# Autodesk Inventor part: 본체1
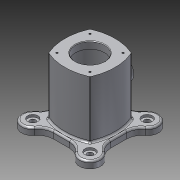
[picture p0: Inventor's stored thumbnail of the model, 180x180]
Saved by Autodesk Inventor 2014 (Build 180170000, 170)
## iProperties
Created: 2016-05
Part Number: 본체1
Material: 알루미늄 6061
Document SubType Name: Modeling
Designer: Administrator
Density: 2.71 g/cm^3
Appearance: 알루미늄 - 평지
Mass: 1111.1 g
Surface Area: 865.598 cm^2
Volume: 409.999 cm^3
Author: Administrator
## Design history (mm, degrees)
sketch "스케치1" dims "d1" = 70
  geometry: L1 (-49, 49)-(49, 49); L2 (49, 49)-(49, -49); L3 (49, -49)-(-49, -49); L4 (-49, -49)-(-49, 49); L5 (0, 0)-(-49.497, 49.497); L6 (0, 0)-(0, 49); C1 r 18 at (-49.497, 49.497); C2 r 18 at (-49.497, -49.497); C3 r 18 at (49.497, -49.497); C4 r 18 at (49.497, 49.497); 2 further points
  constraints: 12 end point, 4 centre point, 3 parallel, 2 midpoint, 1 coincident, 1 horizontal, 1 horizontal alignment, 1 perpendicular, 1 vertical alignment, 12 other
  dimensions: "d2" = 98 distance of L2.end L3.end; "d3" = 98 distance of L1.end L2.end; "d4" = 45 deg angle of L5 L6; "d6" = 18 radius of C1; "d9" = 360 deg dimension on point (0, 0) L5.end (derived)
extrude "돌출1" new body sketch "스케치1" distance "d11" = 12; taper "d12" = 0 deg
hole "구멍1" diameter "d15" = 10; stored, may be unused: countersink angle "d19" = 90 deg, drill point angle "d21" = 118 deg; dims "d13" = 10, "d14" = 10, "d16" = 6, "d17" = 18, "d18" = 4, "d20" = 8
fillet "모깎기1" dims "d28" = 25
sketch "스케치2"
  geometry: L1 (0, 0)-(-28.284, 28.284); L2 (0, 0)-(0, 40); A1 r 40 centre (0, 0) between (0, 40) and (-28.284, 28.284); 2 further points
  constraints: 4 end point, 2 coincident, 2 point on circle, 1 centre point
  dimensions: "d31" = 40 radius of A1; "d32" = 45 deg angle of L2 L1
hole "구멍2" sketch "스케치2" at (-28.284, 28.284) diameter "d33" = 3.242; stored, may be unused: countersink angle "d37" = 90 deg, drill point angle "d39" = 120 deg; dims "d34" = 7, "d35" = 18, "d36" = 4, "d38" = 10
sketch "스케치3"
  geometry: L1 (-43, 43)-(43, 43); L2 (43, 43)-(43, -43); L3 (43, -43)-(-43, -43); L4 (-43, -43)-(-43, 43); L5 (-35.355, 35.355)-(35.355, 35.355); L6 (35.355, 35.355)-(35.355, -35.355); L7 (35.355, -35.355)-(-35.355, -35.355); L8 (-35.355, -35.355)-(-35.355, 35.355); L9 (0, 0)-(-43, 43); L10 (0, 0)-(43, 43); A1 r 85.963 centre (43, 0) between (-35.355, 35.355) and (-35.355, -35.355); A2 r 85.579 centre (0, -42.579) between (35.355, 35.355) and (-35.355, 35.355); A3 r 85.579 centre (-42.579, 0) between (35.355, -35.355) and (35.355, 35.355); A4 r 85.579 centre (0, 42.579) between (-35.355, -35.355) and (35.355, -35.355); 4 further points
  constraints: 20 end point, 11 point on circle, 4 centre point, 4 midpoint, 4 parallel, 2 horizontal, 2 horizontal alignment, 2 perpendicular, 2 vertical alignment, 1 point on line, 1 tangent
  dimensions: "d75" = 86 distance between parallel lines of L4 L2; "d76" = 86 distance between parallel lines of L3 L1; "d78" = 100 distance of L7.end L5.end
extrude "돌출2" join sketch "스케치3" distance "d79" = 98; taper "d80" = 0 deg
sketch "스케치4"
  geometry: 2 further points
  constraints: 1 coincident
hole "구멍3" sketch "스케치4" at (0, 0) diameter "d81" = 50; stored, may be unused: countersink angle "d85" = 90 deg, drill point angle "d87" = 120 deg; dims "d82" = 50, "d83" = 18, "d84" = 4, "d86" = 10
sketch "스케치5"
  geometry: L1 (35, 98)-(0, 98); L2 (0, 98)-(0, 12); L3 (0, 12)-(35, 12); L4 (35, 12)-(35, 98); L5 (-25, 110)-(25, 110) reference; L6 (25, 0)-(-25, 0) reference; L7 (0, 110)-(0, 98); 1 further point
  constraints: 10 end point, 2 parallel, 2 perpendicular, 1 horizontal, 1 midpoint, 1 vertical alignment
  dimensions: "d88" = 70 diameter of L4 L2; "d89" = 12 distance between parallel lines of L5 L1; "d90" = 12 distance between parallel lines of L6 L3
revolve "회전1" sketch "스케치5" stored, may be unused: angle "d91" = 90 deg
sketch "스케치6"
  geometry: L1 (0, 0)-(28.284, 28.284); L2 (0, 0)-(0, 40); C1 r 25 at (0, 0) reference; A1 r 40 centre (0, 0) between (0, 40) and (28.284, 28.284); 1 further point
  constraints: 4 end point, 2 coincident, 2 point on circle, 1 centre point, 1 vertical
  dimensions: "d92" = 40 radius of A1; "d93" = 45 deg angle of L1 L2
hole "구멍4" sketch "스케치6" at (28.284, 28.284) diameter "d94" = 3.242; stored, may be unused: countersink angle "d98" = 90 deg, drill point angle "d100" = 120 deg; dims "d95" = 7, "d96" = 18, "d97" = 4, "d99" = 10
node "작업 평면1"
sketch "스케치7"
  geometry: L1 (0, -22)-(0, 132) reference; L2 (35.355, 110)-(-35.355, 110) reference; C1 r 20 at (0, 61); 1 further point
  constraints: 1 centre point, 1 point on line
  dimensions: "d109" = 40 diameter of C1; "d112" = 49 distance from line of C1.centre L2
extrude "돌출3" join sketch "스케치7" stored distance "d110" = 98; taper "d111" = 10 deg
hole "구멍5" diameter "d115" = 25; stored, may be unused: countersink angle "d119" = 90 deg, drill point angle "d121" = 120 deg; dims "d113" = 10, "d114" = 10, "d116" = 7, "d117" = 30, "d118" = 8, "d120" = 10
node "작업 평면3"
sketch "스케치9"
  geometry: L1 (35.355, 98)-(-35.355, 98) reference; C1 r 12.5 at (0, 49) reference; 2 further points
  constraints: 1 other
  dimensions: "d126" = 29 distance of point (-29, 49) C1.centre; "d127" = 49 distance from line of L1 point (-29, 49)
feature "엠보싱2" sketch "스케치9" dims "d1" = 70, "d2" = 98, "d3" = 98, "d4" = 45 deg, "d6" = 18, "d9" = 360 deg (derived), "d24" = 98 (= d3), "d128" = 0.5, "d129" = 0
fillet "모깎기2" dims "d130" = 3
fillet "모깎기3" dims "d131" = 3
fillet "모깎기4" dims "d132" = 3
chamfer "모따기1" distance "d133" = 1; stored, may be unused: second distance "d134" = 2, angle "d135" = 45 deg
node "솔리드1"
pattern_linear "직사각형 패턴1" dims "d24" = 98 (= d3), "d27" = 98 (= d2)
pattern_circular "원형 패턴1" dims angle "d102" = 360 deg
pattern_circular "원형 패턴2" dims angle "d105" = 360 deg
other parameters: "d107" = 55
